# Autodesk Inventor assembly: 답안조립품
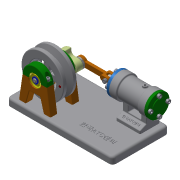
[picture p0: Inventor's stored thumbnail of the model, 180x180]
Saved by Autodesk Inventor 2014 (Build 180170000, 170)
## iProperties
Created: 2018-01
Part Number: 답안조립품
Document SubType Name: Assembly
Designer: Administrator
Author: Administrator
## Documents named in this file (19)
- C:\Users\Administrator\Desktop\380108V1020\답안조립품.iam
- C:\Users\Administrator\Desktop\380108V1020\1-플레이트.ipt
- C:\Users\Administrator\Desktop\380108V1020\2-지지대-A.ipt
- C:\Users\Administrator\Desktop\380108V1020\3-베어링커버-A.ipt
- C:\Users\Administrator\Desktop\380108V1020\4-베어링 8x22x7.ipt
- C:\Users\Administrator\Desktop\380108V1020\5-스페이서.ipt
- C:\Users\Administrator\Desktop\380108V1020\6-V-벨트풀리.ipt
- C:\Users\Administrator\Desktop\380108V1020\7-크랭크축.ipt
- C:\Users\Administrator\Desktop\380108V1020\8-하우징.ipt
- C:\Users\Administrator\Desktop\380108V1020\9-하우징커버-A.ipt
- C:\Users\Administrator\Desktop\380108V1020\10-하우징커버-B.ipt
- C:\Users\Administrator\Desktop\380108V1020\11-플랜지.ipt
- C:\Users\Administrator\Desktop\380108V1020\12-커넥팅로드-A.ipt
- C:\Users\Administrator\Desktop\380108V1020\13-커넥팅로드-B.ipt
- C:\Users\Administrator\Desktop\380108V1020\14-피스톤.ipt
- C:\Users\Administrator\Desktop\380108V1020\15-3mm 와셔.ipt
- C:\Users\Administrator\Desktop\380108V1020\16-볼트 M3x8.ipt
- C:\Users\Administrator\Desktop\380108V1020\17-볼트 M3x12.ipt
- C:\Users\Administrator\Desktop\380108V1020\18-둥근머리볼트 M3x12.ipt
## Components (20 placed, 15 different names)
1. 1-플레이트:1 — Mate:1, Mate:2, Mate:3, Insert:1, Insert:2, Mate:4, Mate:5, Mate:6, Mate:7, Mate:8, Mate:9, Insert:3, Insert:4, Insert:5, Insert:6
2. 2-지지대-A:1 — Mate:4, Mate:5, Mate:6, Mate:10, Mate:11, Mate:12, Insert:7
3. 3-베어링커버-A:1 — Mate:10, Mate:11, Mate:12, Insert:18, Insert:19
4. 4-베어링 8x22x7:1 — Insert:7, Mate:18, Insert:14
5. 5-스페이서:1 — Insert:11, Insert:14
6. 6-V-벨트풀리:1 — Insert:11, Insert:12, Angle:1, 구동부
7. 7-크랭크축:1 — Mate:17, Angle:1, Mate:18, Insert:15, Insert:16, Mate:20, Mate:21
8. 8-하우징:1 — Mate:1, Mate:2, Mate:3, Insert:9, Mate:16, Insert:22, Mate:19, Mate:28
9. 9-하우징커버-A:1 — Insert:22, Mate:19, Insert:23
10. 10-하우징커버-B:1 — Insert:9, Mate:16, Insert:10
11. 11-플랜지:1 — Mate:20, Mate:21, Mate:22, Mate:23, Mate:24
12. 12-커넥팅로드-A:1 — Mate:22, Mate:23, Mate:25, Mate:26, Mate:27, Insert:25
13. 13-커넥팅로드-B:1 — Mate:26, Mate:27, Mate:29, Mate:30
14. 14-피스톤:1 — Mate:28, Mate:29, Mate:30, Insert:26
15. 15-3mm 와셔:1 — Insert:16, Insert:17
16. 2-지지대-A:2 — Mate:7, Mate:8, Mate:9, Mate:13, Mate:14, Mate:15, Insert:8
17. 3-베어링커버-A:2 — Mate:13, Mate:14, Mate:15, Insert:20, Insert:21
18. 4-베어링 8x22x7:2 — Insert:8, Insert:15
19. 5-스페이서:2 — Insert:12, Mate:17
20. 15-3mm 와셔:2 — Mate:24, Mate:25, Insert:24
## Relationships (57: Mate 30, Insert 25, Angle 2)
- Mate:1: 1-플레이트:1 ↔ 8-하우징:1
- Mate:2: 1-플레이트:1 ↔ 8-하우징:1
- Mate:3: 1-플레이트:1 ↔ 8-하우징:1
- Insert:1: 1-플레이트:1
- Insert:2: 1-플레이트:1
- Mate:4: 1-플레이트:1 ↔ 2-지지대-A:1
- Mate:5: 1-플레이트:1 ↔ 2-지지대-A:1
- Mate:6: 1-플레이트:1 ↔ 2-지지대-A:1
- Mate:7: 1-플레이트:1 ↔ 2-지지대-A:2
- Mate:8: 1-플레이트:1 ↔ 2-지지대-A:2
- Mate:9: 1-플레이트:1 ↔ 2-지지대-A:2
- Insert:3: 1-플레이트:1
- Insert:4: 1-플레이트:1
- Insert:5: 1-플레이트:1
- Insert:6: 1-플레이트:1
- Mate:10: 2-지지대-A:1 ↔ 3-베어링커버-A:1
- Mate:11: 2-지지대-A:1 ↔ 3-베어링커버-A:1
- Mate:12: 2-지지대-A:1 ↔ 3-베어링커버-A:1
- Mate:13: 2-지지대-A:2 ↔ 3-베어링커버-A:2
- Mate:14: 2-지지대-A:2 ↔ 3-베어링커버-A:2
- Mate:15: 2-지지대-A:2 ↔ 3-베어링커버-A:2
- Insert:7: 2-지지대-A:1 ↔ 4-베어링 8x22x7:1
- Insert:8: 2-지지대-A:2 ↔ 4-베어링 8x22x7:2
- Insert:9: 8-하우징:1 ↔ 10-하우징커버-B:1
- Mate:16: 8-하우징:1 ↔ 10-하우징커버-B:1
- Insert:10: 10-하우징커버-B:1
- Insert:11: 5-스페이서:1 ↔ 6-V-벨트풀리:1
- Insert:12: 6-V-벨트풀리:1 ↔ 5-스페이서:2
- Mate:17: 7-크랭크축:1 ↔ 5-스페이서:2
- Angle:1: 6-V-벨트풀리:1 ↔ 7-크랭크축:1
- Mate:18: 4-베어링 8x22x7:1 ↔ 7-크랭크축:1
- Insert:14: 4-베어링 8x22x7:1 ↔ 5-스페이서:1
- Insert:15: 7-크랭크축:1 ↔ 4-베어링 8x22x7:2
- Insert:16: 7-크랭크축:1 ↔ 15-3mm 와셔:1
- Insert:17: 15-3mm 와셔:1
- Insert:18: 3-베어링커버-A:1
- Insert:19: 3-베어링커버-A:1
- Insert:20: 3-베어링커버-A:2
- Insert:21: 3-베어링커버-A:2
- Insert:22: 8-하우징:1 ↔ 9-하우징커버-A:1
- Mate:19: 8-하우징:1 ↔ 9-하우징커버-A:1
- Insert:23: 9-하우징커버-A:1
- Mate:20: 7-크랭크축:1 ↔ 11-플랜지:1
- Mate:21: 7-크랭크축:1 ↔ 11-플랜지:1
- Mate:22: 11-플랜지:1 ↔ 12-커넥팅로드-A:1
- Mate:23: 11-플랜지:1 ↔ 12-커넥팅로드-A:1
- Mate:24: 11-플랜지:1 ↔ 15-3mm 와셔:2
- Mate:25: 12-커넥팅로드-A:1 ↔ 15-3mm 와셔:2
- Insert:24: 15-3mm 와셔:2
- Mate:26: 12-커넥팅로드-A:1 ↔ 13-커넥팅로드-B:1
- Mate:27: 12-커넥팅로드-A:1 ↔ 13-커넥팅로드-B:1
- Mate:28: 8-하우징:1 ↔ 14-피스톤:1
- Insert:25: 12-커넥팅로드-A:1
- Mate:29: 13-커넥팅로드-B:1 ↔ 14-피스톤:1
- Mate:30: 13-커넥팅로드-B:1 ↔ 14-피스톤:1
- Insert:26: 14-피스톤:1
- 구동부 [Angle]: 6-V-벨트풀리:1
